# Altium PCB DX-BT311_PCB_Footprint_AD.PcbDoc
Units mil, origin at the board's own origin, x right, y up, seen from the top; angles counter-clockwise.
Board outline 6000 x 4000 mil, 2 copper layers (Top Layer, Bottom Layer); 1 components, 0 nets, 16 pads, 0 vias.
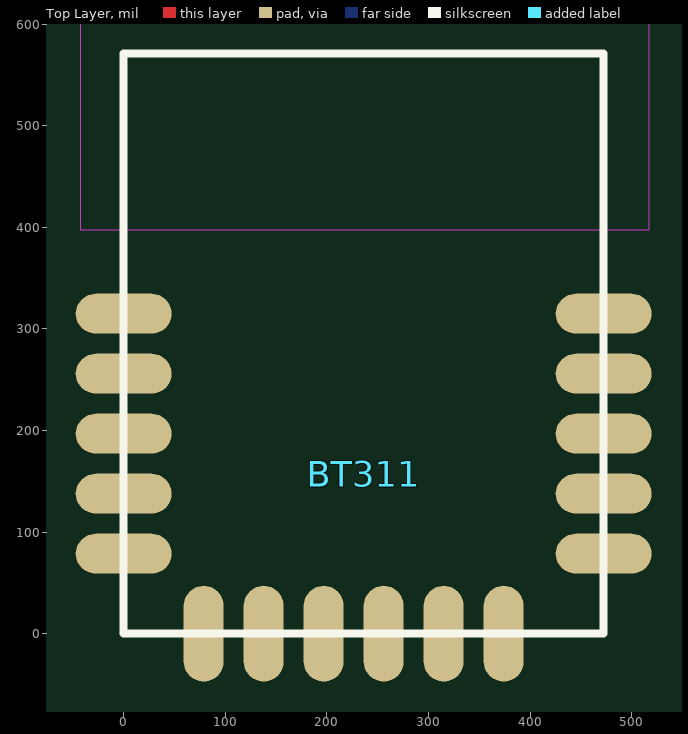
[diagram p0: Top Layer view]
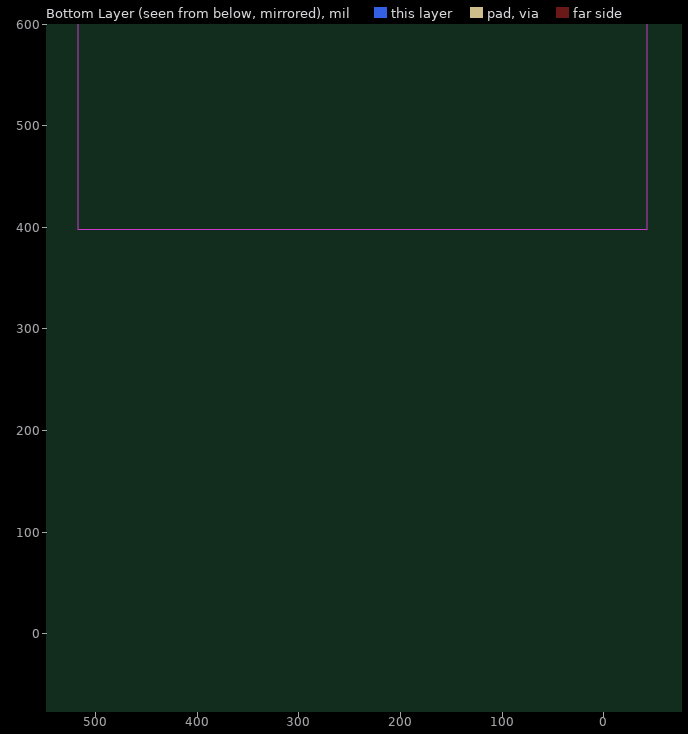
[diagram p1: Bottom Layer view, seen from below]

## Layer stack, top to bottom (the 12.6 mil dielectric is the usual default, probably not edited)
Top Solder: solder mask 0.4, Solder Resist, Dk 3.5
Top Layer: signal copper 1.4
Dielectric 1: dielectric 12.6, FR-4, Dk 4.8
Bottom Layer: signal copper 1.4
Bottom Solder: solder mask 0.4, Solder Resist, Dk 3.5

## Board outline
-2890.09,-2136.67 3109.91,-2136.67 3109.91,1863.33 -2890.09,1863.33

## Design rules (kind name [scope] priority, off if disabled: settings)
Clearance [All] p1: gap=10 ignorepadtopadclearanceinfootprint=FALSE except(0: Arc-Hole Track-Hole SMDPad-Hole THPad-Hole Via-Hole Fill-Hole Poly-Hole Region-Hole Text-Hole)
PolygonConnect [All] p1: connectstyle=Relief reliefconductorwidth=10 reliefentries=4 polygonreliefangle="90 Angle" airgapwidth=10
RoutingVias [All] p1: holewidth=28 width=50 viastyle="Through Hole" minholewidth=28 minwidth=50 maxholewidth=28 maxwidth=50
SolderMaskExpansion [All] p1: expansion=4 istentingtop=FALSE
Width [All] p1: maxlimit=10 minlimit=10 preferedwidth=10
30 further rules are at their usual default settings.

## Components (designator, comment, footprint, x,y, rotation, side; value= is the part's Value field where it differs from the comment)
BT311 "" BT311 0,0 r0 top

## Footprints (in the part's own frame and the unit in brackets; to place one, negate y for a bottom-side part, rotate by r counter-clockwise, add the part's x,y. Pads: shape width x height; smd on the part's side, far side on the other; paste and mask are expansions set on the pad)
BT311 [mm]
  oval 2.4x1 smd mask-2539.97: 1(0,8) 2(0,6.5) 3(0,5) 4(0,3.5) 5(0,2) 12(12,2) 13(12,3.5) 14(12,5) 15(12,6.5) 16(12,8)
  oval 1x2.4 smd mask-2539.97: 6(2,0) 7(3.5,0) 8(5,0) 9(6.5,0) 10(8,0) 11(9.5,0)
  Keep-Out Layer region: -1.081,10.104 13.143,10.104 13.143,15.692 -1.081,15.692
  silkscreen extent 0,0 12,14.5

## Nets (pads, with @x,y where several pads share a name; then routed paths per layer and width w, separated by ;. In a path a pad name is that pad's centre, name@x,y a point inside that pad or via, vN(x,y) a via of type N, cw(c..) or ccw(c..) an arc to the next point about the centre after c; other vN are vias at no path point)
pads on no net: BT311.1 BT311.2 BT311.3 BT311.4 BT311.5 BT311.6 BT311.7 BT311.8 BT311.9 BT311.10 BT311.11 BT311.12 BT311.13 BT311.14 BT311.15 BT311.16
